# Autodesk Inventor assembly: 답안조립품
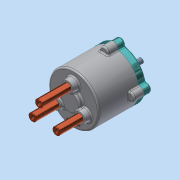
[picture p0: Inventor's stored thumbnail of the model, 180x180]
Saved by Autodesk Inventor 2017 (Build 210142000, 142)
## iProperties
Part Number: 답안조립품
Material: 일반
Document SubType Name: Assembly
Designer: MRC
Author: MRC
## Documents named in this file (14)
- C:\Users\MRC\Desktop\610708V1007\답안조립품.iam
- C:\Users\MRC\Desktop\610708V1007\본체.ipt
- C:\Users\MRC\Desktop\610708V1007\가변스프링1.ipt
- C:\Users\MRC\Desktop\610708V1007\가변스프링2.ipt
- C:\Users\MRC\Desktop\610708V1007\가변스프링3.ipt
- C:\Users\MRC\Desktop\610708V1007\멈춤링 10 x 1.ipt
- C:\Users\MRC\Desktop\610708V1007\멈춤링 22 x 1.2.ipt
- C:\Users\MRC\Desktop\610708V1007\메인 축.ipt
- C:\Users\MRC\Desktop\610708V1007\베어링 NA 4900.ipt
- C:\Users\MRC\Desktop\610708V1007\볼트 M5.ipt
- C:\Users\MRC\Desktop\610708V1007\슬라이드 축.ipt
- C:\Users\MRC\Desktop\610708V1007\오일실.ipt
- C:\Users\MRC\Desktop\610708V1007\커버.ipt
- C:\Users\MRC\Desktop\610708V1007\판캠.ipt
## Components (3 placed, 3 different names)
1. 가변스프링1:1
2. 가변스프링2:1
3. 가변스프링3:1
